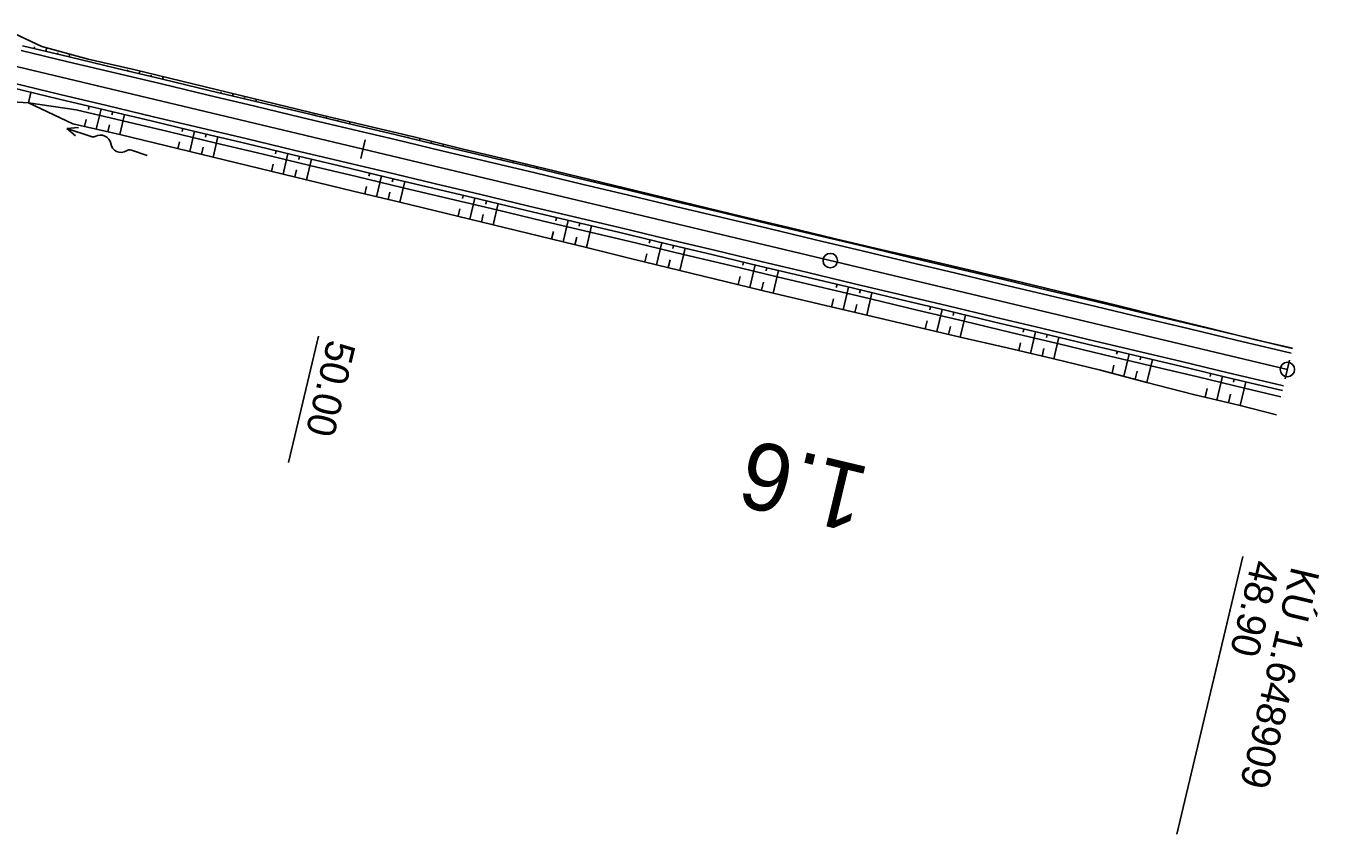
# Model space of a CAD drawing. Extents: x -481645 to -478728, y -1113199 to -1110710.
# Drawn here: x -478863.1 to -478728.5, y -1110802.4 to -1110718.3 of the extents above; entities that cross this region are included whole.
import ezdxf

# ---------------------------------------------------------------- set-up
doc = ezdxf.new("R2010")
doc.units = 0
for name, color, linetype in [('CP14_HATCH_SLOPE_L', 7, 'Continuous'), ('CP14_HECTOMETRY', 7, 'Continuous'), ('CP14_HLBODY', 7, 'Continuous'), ('CP1_HECTOMETRY', 7, 'Continuous'), ('O6_HATCH_SLOPE_L', 7, 'Continuous'), ('O6_HATCH_SLOPE_R', 7, 'Continuous'), ('O6_HECTOMETRY', 7, 'Continuous'), ('O6_HLBODY', 7, 'Continuous'), ('O6_HRANA_TELESO', 7, 'Continuous'), ('O6_OSA', 7, 'Continuous'), ('O6_VOZOVKA', 7, 'Continuous'), ('O6_ZPEVKRAJ', 7, 'Continuous')]:
    doc.layers.add(name, color=color, linetype=linetype)

# ---------------------------------------------------------------- blocks, each defined once
blk = doc.blocks.new('A$C70B')
at = {"layer": 'CP14_HLBODY'}
for p, q in [((0.87, 0), (-0.87, 0)), ((6.86, 0.43), (7.97, 0)), ((7.97, 0), (5.28, 0)), ((7.97, 0), (6.86, -0.48))]:
    blk.add_line(p, q, dxfattribs=at)
for centre, radius, start, end in [((0.87, 0.58), 0.582, 269.6924, 322.7901), ((2.17, -0.42), 1.05, 24.4039, 142.0836), ((4.08, 0.59), 1.11, 210.8873, 317.3707), ((5.32, -0.64), 0.636, 85.9766, 131.7248)]:
    blk.add_arc(centre, radius, start, end, dxfattribs=at)

msp = doc.modelspace()

# ---------------------------------------------------------------- linework, layer by layer
at = {"layer": 'CP14_HATCH_SLOPE_L'}
for p, q in [((-478862.57, -1110725.21), (-478862.82, -1110726.29)), ((-478856.49, -1110726.66), (-478856.56, -1110726.98)), ((-478855.27, -1110726.95), (-478855.77, -1110729.04)), ((-478854.05, -1110727.24), (-478854.13, -1110727.56)), ((-478852.84, -1110727.53), (-478853.33, -1110729.6)), ((-478856.81, -1110728.03), (-478856.99, -1110728.76)), ((-478854.38, -1110728.6), (-478854.55, -1110729.32)), ((-478846.76, -1110728.98), (-478846.84, -1110729.3)), ((-478845.54, -1110729.26), (-478846.04, -1110731.36)), ((-478844.33, -1110729.55), (-478844.4, -1110729.88)), ((-478843.11, -1110729.84), (-478843.61, -1110731.95)), ((-478847.09, -1110730.35), (-478847.26, -1110731.07)), ((-478844.65, -1110730.93), (-478844.83, -1110731.66)), ((-478837.03, -1110731.29), (-478837.11, -1110731.62)), ((-478835.82, -1110731.58), (-478836.32, -1110733.72)), ((-478837.36, -1110732.68), (-478837.54, -1110733.43)), ((-478834.6, -1110731.87), (-478834.68, -1110732.2)), ((-478833.38, -1110732.16), (-478833.89, -1110734.31)), ((-478834.93, -1110733.27), (-478835.11, -1110734.01)), ((-478827.3, -1110733.61), (-478827.38, -1110733.93)), ((-478826.09, -1110733.9), (-478826.6, -1110736.07)), ((-478824.87, -1110734.19), (-478824.95, -1110734.51)), ((-478827.64, -1110735.02), (-478827.82, -1110735.78)), ((-478825.21, -1110735.6), (-478825.39, -1110736.36)), ((-478823.66, -1110734.48), (-478824.17, -1110736.65)), ((-478817.58, -1110735.93), (-478817.65, -1110736.25)), ((-478816.36, -1110736.22), (-478816.88, -1110738.41)), ((-478815.14, -1110736.51), (-478815.22, -1110736.83)), ((-478813.93, -1110736.79), (-478814.45, -1110739)), ((-478817.91, -1110737.34), (-478818.1, -1110738.11)), ((-478815.48, -1110737.93), (-478815.67, -1110738.71)), ((-478807.85, -1110738.24), (-478807.92, -1110738.57)), ((-478808.19, -1110739.69), (-478808.38, -1110740.48)), ((-478806.63, -1110738.53), (-478807.17, -1110740.78)), ((-478805.42, -1110738.82), (-478805.49, -1110739.15)), ((-478804.2, -1110739.11), (-478804.74, -1110741.37)), ((-478805.76, -1110740.27), (-478805.95, -1110741.08)), ((-478798.12, -1110740.56), (-478798.2, -1110740.89)), ((-478796.9, -1110740.85), (-478797.45, -1110743.15)), ((-478798.47, -1110742.03), (-478798.67, -1110742.85)), ((-478795.69, -1110741.14), (-478795.76, -1110741.46)), ((-478794.47, -1110741.43), (-478795.02, -1110743.74)), ((-478796.04, -1110742.62), (-478796.24, -1110743.45)), ((-478788.39, -1110742.88), (-478788.47, -1110743.2)), ((-478787.17, -1110743.17), (-478787.73, -1110745.52)), ((-478785.96, -1110743.46), (-478786.04, -1110743.78)), ((-478788.75, -1110744.37), (-478788.95, -1110745.22)), ((-478786.32, -1110744.96), (-478786.52, -1110745.81)), ((-478784.74, -1110743.75), (-478785.31, -1110746.11)), ((-478778.66, -1110745.2), (-478778.74, -1110745.52)), ((-478777.45, -1110745.49), (-478778.01, -1110747.83)), ((-478776.23, -1110745.77), (-478776.31, -1110746.1)), ((-478775.02, -1110746.06), (-478775.57, -1110748.4)), ((-478779.02, -1110746.7), (-478779.22, -1110747.55)), ((-478776.59, -1110747.27), (-478776.79, -1110748.12)), ((-478768.94, -1110747.51), (-478769.01, -1110747.84)), ((-478769.29, -1110748.99), (-478769.49, -1110749.82)), ((-478767.72, -1110747.8), (-478768.27, -1110750.11)), ((-478766.5, -1110748.09), (-478766.58, -1110748.42)), ((-478765.29, -1110748.38), (-478765.83, -1110750.67)), ((-478766.85, -1110749.56), (-478767.05, -1110750.39)), ((-478759.21, -1110749.83), (-478759.29, -1110750.15)), ((-478757.99, -1110750.12), (-478758.53, -1110752.37)), ((-478756.78, -1110750.41), (-478756.85, -1110750.73)), ((-478759.55, -1110751.28), (-478759.75, -1110752.09)), ((-478755.56, -1110750.7), (-478756.09, -1110752.94)), ((-478757.12, -1110751.86), (-478757.31, -1110752.65)), ((-478749.48, -1110752.15), (-478749.56, -1110752.47)), ((-478748.26, -1110752.44), (-478748.82, -1110754.75)), ((-478747.05, -1110752.73), (-478747.12, -1110753.05)), ((-478745.83, -1110753.02), (-478746.4, -1110755.4)), ((-478749.83, -1110753.61), (-478750.02, -1110754.43)), ((-478747.41, -1110754.22), (-478747.61, -1110755.07)), ((-478739.75, -1110754.46), (-478739.83, -1110754.79)), ((-478738.54, -1110754.75), (-478739.13, -1110757.23)), ((-478737.32, -1110755.04), (-478737.4, -1110755.37)), ((-478736.1, -1110755.33), (-478736.7, -1110757.81)), ((-478740.12, -1110756.02), (-478740.34, -1110756.94)), ((-478737.69, -1110756.61), (-478737.91, -1110757.52))]:
    msp.add_line(p, q, dxfattribs=at)
at = {"layer": 'CP1_HECTOMETRY'}
msp.add_line((-478877.17, -1110719.42), (-478731.78, -1110754.05), dxfattribs=at)
at = {"layer": 'O6_HATCH_SLOPE_L'}
msp.add_circle((-478779.36, -1110742.72), 0.75, dxfattribs=at)
at = {"layer": 'O6_HATCH_SLOPE_R'}
for p, q in [((-478862.24, -1110720.66), (-478862.2, -1110720.48)), ((-478862.16, -1110720.3), (-478862.16, -1110720.3)), ((-478861.03, -1110720.95), (-478860.95, -1110720.63)), ((-478859.81, -1110721.24), (-478859.78, -1110721.1)), ((-478859.75, -1110720.96), (-478859.75, -1110720.96)), ((-478858.6, -1110721.53), (-478858.54, -1110721.29)), ((-478852.52, -1110722.98), (-478852.49, -1110722.85)), ((-478852.46, -1110722.73), (-478852.46, -1110722.73)), ((-478851.3, -1110723.27), (-478851.24, -1110723.02)), ((-478850.09, -1110723.56), (-478850.06, -1110723.43)), ((-478850.03, -1110723.31), (-478850.03, -1110723.31)), ((-478848.87, -1110723.85), (-478848.81, -1110723.6)), ((-478842.79, -1110725.29), (-478842.76, -1110725.18)), ((-478842.73, -1110725.06), (-478842.73, -1110725.06)), ((-478841.57, -1110725.58), (-478841.52, -1110725.36)), ((-478840.36, -1110725.87), (-478840.33, -1110725.76)), ((-478840.3, -1110725.65), (-478840.3, -1110725.65)), ((-478839.14, -1110726.16), (-478839.09, -1110725.94)), ((-478833.06, -1110727.61), (-478833.04, -1110727.51)), ((-478833.01, -1110727.4), (-478833.01, -1110727.4)), ((-478831.85, -1110727.9), (-478831.8, -1110727.7)), ((-478830.63, -1110728.19), (-478830.61, -1110728.09)), ((-478830.58, -1110727.99), (-478830.58, -1110727.99)), ((-478829.41, -1110728.48), (-478829.37, -1110728.28)), ((-478823.33, -1110729.93), (-478823.31, -1110729.83)), ((-478823.29, -1110729.73), (-478823.29, -1110729.73)), ((-478822.12, -1110730.22), (-478822.07, -1110730.03)), ((-478820.9, -1110730.51), (-478820.88, -1110730.41)), ((-478820.86, -1110730.32), (-478820.86, -1110730.32)), ((-478819.69, -1110730.8), (-478819.64, -1110730.61)), ((-478813.61, -1110732.25), (-478813.59, -1110732.16)), ((-478813.57, -1110732.08), (-478813.57, -1110732.08)), ((-478812.39, -1110732.54), (-478812.35, -1110732.37)), ((-478811.17, -1110732.82), (-478811.16, -1110732.75)), ((-478811.14, -1110732.67), (-478811.14, -1110732.67)), ((-478809.96, -1110733.11), (-478809.92, -1110732.96)), ((-478803.88, -1110734.56), (-478803.86, -1110734.5)), ((-478803.85, -1110734.43), (-478803.85, -1110734.43)), ((-478802.66, -1110734.85), (-478802.63, -1110734.72)), ((-478801.45, -1110735.14), (-478801.43, -1110735.08)), ((-478801.42, -1110735.02), (-478801.42, -1110735.02)), ((-478800.23, -1110735.43), (-478800.2, -1110735.31)), ((-478794.15, -1110736.88), (-478794.14, -1110736.83)), ((-478794.13, -1110736.78), (-478794.13, -1110736.78)), ((-478792.93, -1110737.17), (-478792.91, -1110737.07)), ((-478791.72, -1110737.46), (-478791.71, -1110737.41)), ((-478791.7, -1110737.36), (-478791.7, -1110737.36)), ((-478790.5, -1110737.75), (-478790.48, -1110737.66)), ((-478784.42, -1110739.2), (-478784.41, -1110739.16)), ((-478784.4, -1110739.12), (-478784.4, -1110739.12)), ((-478783.21, -1110739.49), (-478783.19, -1110739.41)), ((-478781.99, -1110739.78), (-478781.98, -1110739.74)), ((-478781.97, -1110739.7), (-478781.97, -1110739.7)), ((-478780.78, -1110740.07), (-478780.76, -1110739.99)), ((-478774.7, -1110741.52), (-478774.68, -1110741.46)), ((-478774.67, -1110741.41), (-478774.67, -1110741.41)), ((-478773.48, -1110741.8), (-478773.45, -1110741.7)), ((-478772.26, -1110742.09), (-478772.25, -1110742.04)), ((-478772.24, -1110741.98), (-478772.24, -1110741.98)), ((-478771.05, -1110742.38), (-478771.02, -1110742.27)), ((-478764.93, -1110743.7), (-478764.93, -1110743.7)), ((-478764.97, -1110743.83), (-478764.95, -1110743.76)), ((-478763.75, -1110744.12), (-478763.72, -1110743.98)), ((-478762.54, -1110744.41), (-478762.52, -1110744.34)), ((-478762.5, -1110744.27), (-478762.5, -1110744.27)), ((-478761.32, -1110744.7), (-478761.28, -1110744.55)), ((-478755.24, -1110746.15), (-478755.22, -1110746.07)), ((-478755.2, -1110745.99), (-478755.2, -1110745.99)), ((-478754.02, -1110746.44), (-478753.99, -1110746.29)), ((-478752.81, -1110746.73), (-478752.79, -1110746.66)), ((-478752.77, -1110746.58), (-478752.77, -1110746.58)), ((-478751.59, -1110747.02), (-478751.56, -1110746.88)), ((-478745.51, -1110748.47), (-478745.5, -1110748.43)), ((-478745.49, -1110748.39), (-478745.49, -1110748.39)), ((-478744.29, -1110748.76), (-478744.28, -1110748.7)), ((-478743.08, -1110749.05), (-478743.08, -1110749.03)), ((-478743.07, -1110749.01), (-478743.07, -1110749.01)), ((-478741.86, -1110749.33), (-478741.86, -1110749.32)), ((-478735.78, -1110750.76), (-478735.78, -1110750.76)), ((-478735.78, -1110750.78), (-478735.78, -1110750.77)), ((-478734.57, -1110751.07), (-478734.56, -1110751.05)), ((-478733.35, -1110751.34), (-478733.35, -1110751.34)), ((-478733.35, -1110751.36), (-478733.35, -1110751.35)), ((-478732.14, -1110751.65), (-478732.13, -1110751.63))]:
    msp.add_line(p, q, dxfattribs=at)
at = {"layer": 'O6_HECTOMETRY'}
msp.add_line((-478736.41, -1110773.51), (-478743.3, -1110802.4), dxfattribs=at)
msp.add_circle((-478731.78, -1110754.05), 0.75, dxfattribs=at)
at = {"layer": 'O6_HLBODY'}
for p, q in [((-478828.23, -1110732.1), (-478827.77, -1110730.16)), ((-478832.63, -1110750.59), (-478835.76, -1110763.72)), ((-478732.02, -1110755.02), (-478731.56, -1110753.07)), ((-478736.42, -1110773.5), (-478739.55, -1110786.64))]:
    msp.add_line(p, q, dxfattribs=at)
at = {"layer": 'O6_HRANA_TELESO'}
for p, q in [((-478862.82, -1110726.29), (-478857.86, -1110727.02)), ((-478857.86, -1110727.02), (-478852.99, -1110728.18)), ((-478852.99, -1110728.18), (-478848.13, -1110729.33)), ((-478848.13, -1110729.33), (-478843.27, -1110730.49)), ((-478843.27, -1110730.49), (-478838.4, -1110731.65)), ((-478838.4, -1110731.65), (-478833.54, -1110732.81)), ((-478833.54, -1110732.81), (-478828.67, -1110733.97)), ((-478828.67, -1110733.97), (-478823.81, -1110735.13)), ((-478823.81, -1110735.13), (-478818.95, -1110736.28)), ((-478818.95, -1110736.28), (-478814.08, -1110737.44)), ((-478814.08, -1110737.44), (-478809.22, -1110738.6)), ((-478809.22, -1110738.6), (-478804.35, -1110739.76)), ((-478804.35, -1110739.76), (-478799.49, -1110740.92)), ((-478799.49, -1110740.92), (-478794.63, -1110742.08)), ((-478794.63, -1110742.08), (-478789.76, -1110743.24)), ((-478789.76, -1110743.24), (-478784.9, -1110744.4)), ((-478784.9, -1110744.4), (-478780.03, -1110745.55)), ((-478780.03, -1110745.55), (-478775.17, -1110746.71)), ((-478775.17, -1110746.71), (-478770.31, -1110747.87)), ((-478770.31, -1110747.87), (-478765.44, -1110749.03)), ((-478765.44, -1110749.03), (-478760.58, -1110750.19)), ((-478760.58, -1110750.19), (-478755.71, -1110751.35)), ((-478755.71, -1110751.35), (-478750.85, -1110752.51)), ((-478750.85, -1110752.51), (-478745.99, -1110753.66)), ((-478745.99, -1110753.66), (-478741.12, -1110754.82)), ((-478741.12, -1110754.82), (-478736.26, -1110755.98)), ((-478736.26, -1110755.98), (-478732.47, -1110756.89))]:
    msp.add_line(p, q, dxfattribs=at)
at = {"layer": 'O6_OSA'}
for p, q in [((-478866.06, -1110718.29), (-478861.43, -1110720.45)), ((-478861.43, -1110720.45), (-478856.6, -1110721.75)), ((-478856.6, -1110721.75), (-478851.73, -1110722.88)), ((-478851.73, -1110722.88), (-478846.87, -1110724.05)), ((-478846.87, -1110724.05), (-478842.01, -1110725.22)), ((-478867.9, -1110726), (-478862.82, -1110726.29)), ((-478842.01, -1110725.22), (-478837.15, -1110726.4)), ((-478862.82, -1110726.29), (-478858.21, -1110728.48)), ((-478837.15, -1110726.4), (-478832.29, -1110727.57)), ((-478832.29, -1110727.57), (-478827.43, -1110728.73)), ((-478858.21, -1110728.48), (-478853.33, -1110729.6)), ((-478827.43, -1110728.73), (-478822.56, -1110729.89)), ((-478853.33, -1110729.6), (-478848.47, -1110730.77)), ((-478822.56, -1110729.89), (-478817.7, -1110731.07)), ((-478848.47, -1110730.77), (-478843.61, -1110731.95)), ((-478817.7, -1110731.07), (-478812.84, -1110732.24)), ((-478843.61, -1110731.95), (-478838.75, -1110733.13)), ((-478812.84, -1110732.24), (-478807.98, -1110733.42)), ((-478838.75, -1110733.13), (-478833.89, -1110734.31)), ((-478807.98, -1110733.42), (-478803.12, -1110734.59)), ((-478833.89, -1110734.31), (-478829.04, -1110735.49)), ((-478829.04, -1110735.49), (-478824.17, -1110736.65)), ((-478803.12, -1110734.59), (-478798.26, -1110735.77)), ((-478824.17, -1110736.65), (-478819.31, -1110737.82)), ((-478798.26, -1110735.77), (-478793.4, -1110736.94)), ((-478793.4, -1110736.94), (-478788.54, -1110738.12)), ((-478819.31, -1110737.82), (-478814.45, -1110739)), ((-478788.54, -1110738.12), (-478783.68, -1110739.29)), ((-478814.45, -1110739), (-478809.6, -1110740.19)), ((-478783.68, -1110739.29), (-478778.82, -1110740.44)), ((-478809.6, -1110740.19), (-478804.74, -1110741.37)), ((-478778.82, -1110740.44), (-478773.95, -1110741.58)), ((-478804.74, -1110741.37), (-478799.88, -1110742.56)), ((-478773.95, -1110741.58), (-478769.08, -1110742.72)), ((-478799.88, -1110742.56), (-478795.02, -1110743.74)), ((-478769.08, -1110742.72), (-478764.21, -1110743.86)), ((-478795.02, -1110743.74), (-478790.16, -1110744.93)), ((-478790.16, -1110744.93), (-478785.31, -1110746.11)), ((-478764.21, -1110743.86), (-478759.34, -1110745)), ((-478759.34, -1110745), (-478754.48, -1110746.17)), ((-478785.31, -1110746.11), (-478780.44, -1110747.26)), ((-478754.48, -1110746.17), (-478749.62, -1110747.35)), ((-478780.44, -1110747.26), (-478775.57, -1110748.4)), ((-478749.62, -1110747.35), (-478744.77, -1110748.57)), ((-478775.57, -1110748.4), (-478770.7, -1110749.54)), ((-478744.77, -1110748.57), (-478739.92, -1110749.76)), ((-478770.7, -1110749.54), (-478765.83, -1110750.67)), ((-478739.92, -1110749.76), (-478735.06, -1110750.95)), ((-478765.83, -1110750.67), (-478760.96, -1110751.81)), ((-478735.06, -1110750.95), (-478731.26, -1110751.83)), ((-478760.96, -1110751.81), (-478756.09, -1110752.94)), ((-478756.09, -1110752.94), (-478751.23, -1110754.11)), ((-478751.23, -1110754.11), (-478746.4, -1110755.4)), ((-478746.4, -1110755.4), (-478741.56, -1110756.65)), ((-478741.56, -1110756.65), (-478736.7, -1110757.81)), ((-478736.7, -1110757.81), (-478732.91, -1110758.76))]:
    msp.add_line(p, q, dxfattribs=at)
at = {"layer": 'O6_VOZOVKA'}
for p, q in [((-478863.58, -1110720.86), (-478858.71, -1110722.02)), ((-478858.71, -1110722.02), (-478853.85, -1110723.17)), ((-478853.85, -1110723.17), (-478848.98, -1110724.33)), ((-478864.39, -1110724.26), (-478859.52, -1110725.42)), ((-478848.98, -1110724.33), (-478844.12, -1110725.49)), ((-478859.52, -1110725.42), (-478854.66, -1110726.58)), ((-478844.12, -1110725.49), (-478839.26, -1110726.65)), ((-478854.66, -1110726.58), (-478849.8, -1110727.74)), ((-478839.26, -1110726.65), (-478834.39, -1110727.81)), ((-478849.8, -1110727.74), (-478844.93, -1110728.9)), ((-478844.93, -1110728.9), (-478840.07, -1110730.05)), ((-478834.39, -1110727.81), (-478829.53, -1110728.97)), ((-478840.07, -1110730.05), (-478835.2, -1110731.21)), ((-478829.53, -1110728.97), (-478824.67, -1110730.12)), ((-478824.67, -1110730.12), (-478819.8, -1110731.28)), ((-478835.2, -1110731.21), (-478830.34, -1110732.37)), ((-478819.8, -1110731.28), (-478814.94, -1110732.44)), ((-478830.34, -1110732.37), (-478825.48, -1110733.53)), ((-478814.94, -1110732.44), (-478810.07, -1110733.6)), ((-478825.48, -1110733.53), (-478820.61, -1110734.69)), ((-478810.07, -1110733.6), (-478805.21, -1110734.76)), ((-478820.61, -1110734.69), (-478815.75, -1110735.85)), ((-478805.21, -1110734.76), (-478800.35, -1110735.92)), ((-478815.75, -1110735.85), (-478810.89, -1110737.01)), ((-478800.35, -1110735.92), (-478795.48, -1110737.08)), ((-478810.89, -1110737.01), (-478806.02, -1110738.17)), ((-478806.02, -1110738.17), (-478801.16, -1110739.32)), ((-478795.48, -1110737.08), (-478790.62, -1110738.24)), ((-478790.62, -1110738.24), (-478785.75, -1110739.39)), ((-478801.16, -1110739.32), (-478796.29, -1110740.48)), ((-478785.75, -1110739.39), (-478780.89, -1110740.55)), ((-478796.29, -1110740.48), (-478791.43, -1110741.64)), ((-478780.89, -1110740.55), (-478776.03, -1110741.71)), ((-478791.43, -1110741.64), (-478786.57, -1110742.8)), ((-478776.03, -1110741.71), (-478771.16, -1110742.87)), ((-478786.57, -1110742.8), (-478781.7, -1110743.96)), ((-478771.16, -1110742.87), (-478766.3, -1110744.03)), ((-478781.7, -1110743.96), (-478776.84, -1110745.12)), ((-478766.3, -1110744.03), (-478761.43, -1110745.19)), ((-478776.84, -1110745.12), (-478771.97, -1110746.27)), ((-478771.97, -1110746.27), (-478767.11, -1110747.43)), ((-478761.43, -1110745.19), (-478756.57, -1110746.35)), ((-478756.57, -1110746.35), (-478751.71, -1110747.5)), ((-478767.11, -1110747.43), (-478762.25, -1110748.59)), ((-478751.71, -1110747.5), (-478746.84, -1110748.66)), ((-478762.25, -1110748.59), (-478757.38, -1110749.75)), ((-478746.84, -1110748.66), (-478741.98, -1110749.82)), ((-478757.38, -1110749.75), (-478752.52, -1110750.91)), ((-478741.98, -1110749.82), (-478737.11, -1110750.98)), ((-478752.52, -1110750.91), (-478747.65, -1110752.07)), ((-478737.11, -1110750.98), (-478732.25, -1110752.14)), ((-478747.65, -1110752.07), (-478742.79, -1110753.23)), ((-478732.25, -1110752.14), (-478731.38, -1110752.35)), ((-478742.79, -1110753.23), (-478737.93, -1110754.39)), ((-478737.93, -1110754.39), (-478733.06, -1110755.54)), ((-478733.06, -1110755.54), (-478732.19, -1110755.75))]:
    msp.add_line(p, q, dxfattribs=at)
at = {"layer": 'O6_ZPEVKRAJ'}
for p, q in [((-478863.46, -1110720.37), (-478858.6, -1110721.53)), ((-478858.6, -1110721.53), (-478853.73, -1110722.69)), ((-478853.73, -1110722.69), (-478848.87, -1110723.85)), ((-478864.5, -1110724.75), (-478859.64, -1110725.91)), ((-478848.87, -1110723.85), (-478844.01, -1110725.01)), ((-478859.64, -1110725.91), (-478854.78, -1110727.06)), ((-478844.01, -1110725.01), (-478839.14, -1110726.16)), ((-478839.14, -1110726.16), (-478834.28, -1110727.32)), ((-478854.78, -1110727.06), (-478849.91, -1110728.22)), ((-478834.28, -1110727.32), (-478829.41, -1110728.48)), ((-478849.91, -1110728.22), (-478845.05, -1110729.38)), ((-478829.41, -1110728.48), (-478824.55, -1110729.64)), ((-478845.05, -1110729.38), (-478840.18, -1110730.54)), ((-478824.55, -1110729.64), (-478819.69, -1110730.8)), ((-478840.18, -1110730.54), (-478835.32, -1110731.7)), ((-478819.69, -1110730.8), (-478814.82, -1110731.96)), ((-478835.32, -1110731.7), (-478830.46, -1110732.86)), ((-478830.46, -1110732.86), (-478825.59, -1110734.02)), ((-478814.82, -1110731.96), (-478809.96, -1110733.11)), ((-478825.59, -1110734.02), (-478820.73, -1110735.18)), ((-478809.96, -1110733.11), (-478805.09, -1110734.27)), ((-478805.09, -1110734.27), (-478800.23, -1110735.43)), ((-478820.73, -1110735.18), (-478815.86, -1110736.33)), ((-478800.23, -1110735.43), (-478795.37, -1110736.59)), ((-478815.86, -1110736.33), (-478811, -1110737.49)), ((-478795.37, -1110736.59), (-478790.5, -1110737.75)), ((-478811, -1110737.49), (-478806.14, -1110738.65)), ((-478790.5, -1110737.75), (-478785.64, -1110738.91)), ((-478806.14, -1110738.65), (-478801.27, -1110739.81)), ((-478785.64, -1110738.91), (-478780.78, -1110740.07)), ((-478801.27, -1110739.81), (-478796.41, -1110740.97)), ((-478796.41, -1110740.97), (-478791.54, -1110742.13)), ((-478780.78, -1110740.07), (-478775.91, -1110741.23)), ((-478791.54, -1110742.13), (-478786.68, -1110743.28)), ((-478775.91, -1110741.23), (-478771.05, -1110742.38)), ((-478786.68, -1110743.28), (-478781.82, -1110744.44)), ((-478771.05, -1110742.38), (-478766.18, -1110743.54)), ((-478766.18, -1110743.54), (-478761.32, -1110744.7)), ((-478781.82, -1110744.44), (-478776.95, -1110745.6)), ((-478761.32, -1110744.7), (-478756.46, -1110745.86)), ((-478776.95, -1110745.6), (-478772.09, -1110746.76)), ((-478756.46, -1110745.86), (-478751.59, -1110747.02)), ((-478772.09, -1110746.76), (-478767.23, -1110747.92)), ((-478751.59, -1110747.02), (-478746.73, -1110748.18)), ((-478767.23, -1110747.92), (-478762.36, -1110749.08)), ((-478762.36, -1110749.08), (-478757.5, -1110750.24)), ((-478746.73, -1110748.18), (-478741.86, -1110749.33)), ((-478757.5, -1110750.24), (-478752.63, -1110751.4)), ((-478741.86, -1110749.33), (-478737, -1110750.49)), ((-478752.63, -1110751.4), (-478747.77, -1110752.55)), ((-478737, -1110750.49), (-478732.14, -1110751.65)), ((-478732.14, -1110751.65), (-478731.26, -1110751.86)), ((-478747.77, -1110752.55), (-478742.91, -1110753.71)), ((-478742.91, -1110753.71), (-478738.04, -1110754.87)), ((-478738.04, -1110754.87), (-478733.18, -1110756.03)), ((-478733.18, -1110756.03), (-478732.3, -1110756.24))]:
    msp.add_line(p, q, dxfattribs=at)

# ---------------------------------------------------------------- block references
at = {"layer": 'CP14_HECTOMETRY', "rotation": 161.33490466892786}
msp.add_blockref('A$C70B', (-478851.28, -1110731.51), dxfattribs=at)

# ---------------------------------------------------------------- texts
at = {"layer": 'O6_HATCH_SLOPE_L'}
msp.add_text('1.6', height=6.999, rotation=166.5561, dxfattribs=at).set_placement((-478775.04, -1110764.31))
at = {"layer": 'O6_HECTOMETRY'}
msp.add_text('KÚ 1.648909', height=2.999, rotation=256.6017, dxfattribs=at).set_placement((-478731.32, -1110774.44))
at = {"layer": 'O6_HLBODY'}
for s, p in [('50.00', (-478831.66, -1110750.82)), ('48.90', (-478735.45, -1110773.73))]:
    msp.add_text(s, height=2.999, rotation=256.6017, dxfattribs=at).set_placement(p)

doc.saveas('drawing.dxf')
